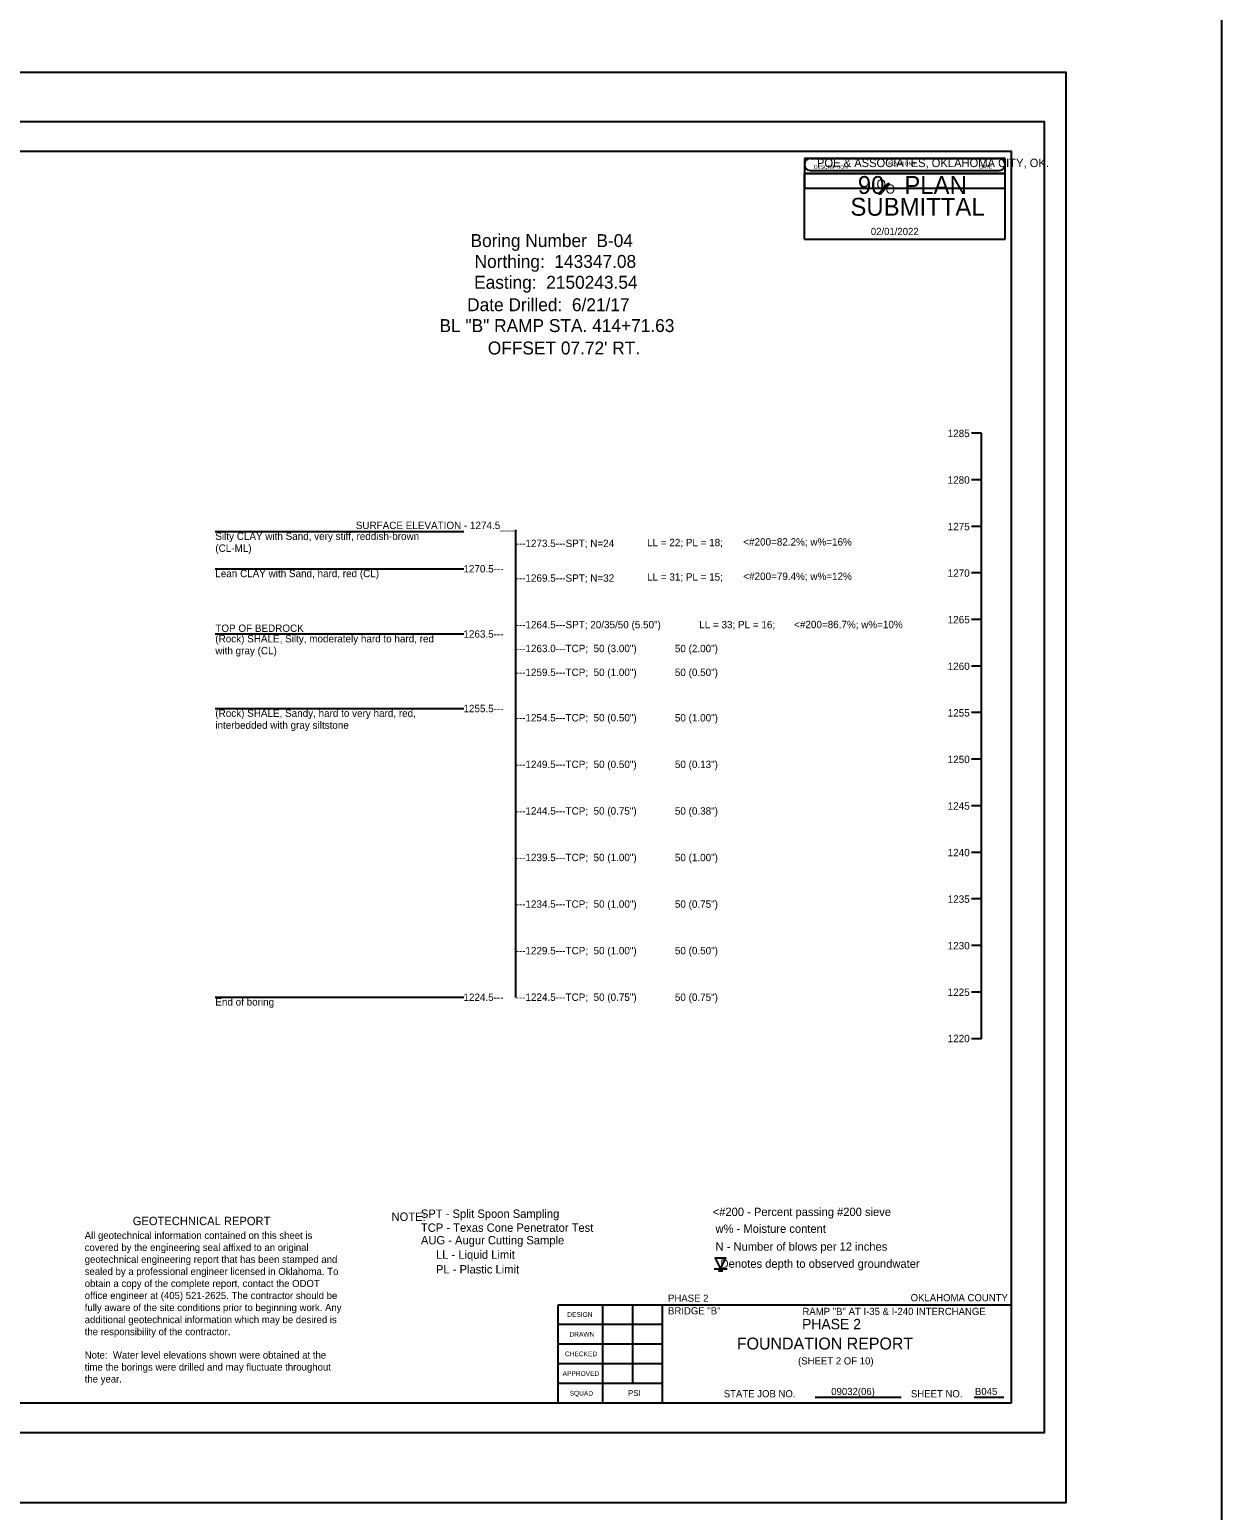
# Model space of a CAD drawing. Extents: x 2150162 to 2150245, y 143729 to 143865.
# Drawn here: x 2150183.41 to 2150203.4, y 143810.76 to 143835.6 of the extents above; entities that cross this region are included whole.
import ezdxf

# ---------------------------------------------------------------- set-up
doc = ezdxf.new("R2010")
doc.units = 0
for name, color, linetype in [('Default', 7, 'Continuous'), ('S', 7, 'Continuous'), ('SHT_Plot_Shape_Full', 7, 'Continuous'), ('SHT_Plot_Shape_Half', 7, 'Continuous'), ('SHT_Sheet_Border', 7, 'Continuous'), ('SHT_Stamp_90_Submit', 7, 'Continuous'), ('SHT_Stamp_Rev_Block', 7, 'Continuous'), ('SHT_Standard_Sheet_Lines', 7, 'Continuous'), ('SHT_Standard_Sheet_Txt', 7, 'Continuous'), ('T', 7, 'Continuous'), ('T-Title', 7, 'Continuous'), ('Text', 7, 'Continuous')]:
    doc.layers.add(name, color=color, linetype=linetype)

# ---------------------------------------------------------------- blocks, each defined once
blk = doc.blocks.new('DGRFC_WTLEV1')
at = {"layer": 'Default'}
for points in [[(-0.0127, 0), (0.0127, 0)], [(0, 0), (0.0106, 0.0212), (-0.0106, 0.0212), (0, 0)], [(-0.0042, -0.0042), (0.0042, -0.0042)]]:
    blk.add_lwpolyline(points, dxfattribs=at)

msp = doc.modelspace()

# ---------------------------------------------------------------- linework, layer by layer
at = {"layer": 'Default'}
msp.add_line((2150199.377, 143818.675), (2150199.377, 143828.832), dxfattribs=at)
for points in [[(2150199.377, 143828.832), (2150199.21, 143828.832)], [(2150199.377, 143828.05), (2150199.21, 143828.05)], [(2150199.377, 143827.269), (2150199.21, 143827.269)], [(2150186.527, 143827.183), (2150190.694, 143827.183)], [(2150191.561, 143827.209), (2150191.561, 143819.364)], [(2150186.527, 143826.558), (2150190.694, 143826.558)], [(2150199.377, 143826.488), (2150199.21, 143826.488)], [(2150199.377, 143825.707), (2150199.21, 143825.707)], [(2150186.527, 143825.464), (2150190.694, 143825.464)], [(2150199.377, 143824.925), (2150199.21, 143824.925)], [(2150186.527, 143824.214), (2150190.694, 143824.214)], [(2150199.377, 143824.144), (2150199.21, 143824.144)], [(2150199.377, 143823.363), (2150199.21, 143823.363)], [(2150199.377, 143822.582), (2150199.21, 143822.582)], [(2150199.377, 143821.8), (2150199.21, 143821.8)], [(2150199.377, 143821.019), (2150199.21, 143821.019)], [(2150199.377, 143820.238), (2150199.21, 143820.238)], [(2150186.527, 143819.37), (2150190.694, 143819.37)], [(2150199.377, 143819.457), (2150199.21, 143819.457)], [(2150199.377, 143818.675), (2150199.21, 143818.675)]]:
    msp.add_lwpolyline(points, dxfattribs=at)
at = {"layer": 'S'}
msp.add_lwpolyline([(2150203.404, 143784.341), (2150161.568, 143784.341), (2150161.568, 143865.061), (2150203.404, 143865.061)], close=True, dxfattribs=at)
at = {"layer": 'SHT_Plot_Shape_Full'}
msp.add_lwpolyline([(2150164.792, 143834.888), (2150200.792, 143834.888), (2150200.792, 143810.888), (2150164.792, 143810.888)], close=True, dxfattribs=at)
at = {"layer": 'SHT_Plot_Shape_Half'}
msp.add_lwpolyline([(2150166.429, 143834.063), (2150200.429, 143834.063), (2150200.429, 143812.063), (2150166.429, 143812.063)], close=True, dxfattribs=at)
at = {"layer": 'SHT_Sheet_Border'}
for p, q in [((2150192.279, 143812.563), (2150192.279, 143814.213)), ((2150192.279, 143814.213), (2150199.879, 143814.213)), ((2150194.029, 143812.563), (2150194.029, 143814.213))]:
    msp.add_line(p, q, dxfattribs=at)
msp.add_lwpolyline([(2150199.879, 143812.563), (2150168.379, 143812.563), (2150168.379, 143833.563), (2150199.879, 143833.563)], close=True, dxfattribs=at)
at = {"layer": 'SHT_Stamp_90_Submit'}
for p, q in [((2150196.51, 143833.438), (2150199.676, 143833.438)), ((2150196.41, 143833.188), (2150199.776, 143833.188)), ((2150196.41, 143832.089), (2150196.41, 143833.188)), ((2150196.51, 143833.238), (2150199.676, 143833.238)), ((2150199.776, 143832.089), (2150199.776, 143833.188)), ((2150197.653, 143832.85), (2150197.809, 143833.023)), ((2150197.671, 143832.85), (2150197.827, 143833.023)), ((2150197.676, 143832.85), (2150197.832, 143833.023)), ((2150197.684, 143832.85), (2150197.839, 143833.023)), ((2150197.809, 143833.023), (2150197.839, 143833.023)), ((2150197.653, 143832.85), (2150197.684, 143832.85)), ((2150196.41, 143832.089), (2150199.776, 143832.089))]:
    msp.add_line(p, q, dxfattribs=at)
for centre, start, end in [((2150196.51, 143833.339), 89.9952, 270), ((2150199.676, 143833.339), 270, 90.0048)]:
    msp.add_arc(centre, 0.1, start, end, dxfattribs=at)
at = {"layer": 'SHT_Stamp_Rev_Block'}
for p, q in [((2150196.41, 143833.438), (2150196.41, 143832.938)), ((2150199.776, 143833.438), (2150196.41, 143833.438)), ((2150199.776, 143832.938), (2150199.776, 143833.438)), ((2150199.776, 143833.188), (2150196.41, 143833.188)), ((2150199.776, 143832.938), (2150196.41, 143832.938))]:
    msp.add_line(p, q, dxfattribs=at)
at = {"layer": 'SHT_Standard_Sheet_Lines'}
for p, q in [((2150193.029, 143812.563), (2150193.029, 143814.213)), ((2150193.529, 143812.893), (2150193.529, 143814.213)), ((2150196.59, 143812.659), (2150198.03, 143812.659)), ((2150199.255, 143812.659), (2150199.757, 143812.659))]:
    msp.add_line(p, q, dxfattribs=at)
for points in [[(2150194.029, 143813.883), (2150192.279, 143813.883)], [(2150194.029, 143813.553), (2150192.279, 143813.553)], [(2150194.029, 143813.223), (2150192.279, 143813.223)], [(2150194.029, 143812.893), (2150192.279, 143812.893)]]:
    msp.add_lwpolyline(points, dxfattribs=at)

# ---------------------------------------------------------------- block references
at = {"layer": 'Default', "xscale": 8.503919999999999, "yscale": 8.503919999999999}
msp.add_blockref('DGRFC_WTLEV1', (2150195.003, 143814.814), dxfattribs=at)

# ---------------------------------------------------------------- texts
at = {"layer": 'Default'}
for s, height, p in [('Boring Number  B-04', 0.217, (2150190.808, 143831.955)), ('Northing:  143347.08', 0.217, (2150190.876, 143831.605)), ('Easting:  2150243.54', 0.217, (2150190.868, 143831.255)), ('Date Drilled:  6/21/17', 0.217, (2150190.751, 143830.879)), ('BL "B" RAMP STA. 414+71.63', 0.217, (2150190.288, 143830.529)), ("OFFSET 07.72' RT.", 0.217, (2150191.098, 143830.153)), ('1285', 0.124, (2150198.813, 143828.767)), ('1280', 0.124, (2150198.813, 143827.985)), ('SURFACE ELEVATION - 1274.5___', 0.124, (2150188.883, 143827.224)), ('1275', 0.124, (2150198.813, 143827.204)), ('Silty CLAY with Sand, very stiff, reddish-brown', 0.124, (2150186.527, 143827.042)), ('(CL-ML)', 0.124, (2150186.527, 143826.842)), ('---1273.5---SPT; N=24', 0.124, (2150191.564, 143826.922)), ('LL = 22; PL = 18;', 0.124, (2150193.77, 143826.936)), ('<#200=82.2%; w%=16%', 0.124, (2150195.384, 143826.947)), ('Lean CLAY with Sand, hard, red (CL)', 0.124, (2150186.527, 143826.417)), ('1270.5---', 0.124, (2150190.689, 143826.496)), ('LL = 31; PL = 15;', 0.124, (2150193.77, 143826.359)), ('<#200=79.4%; w%=12%', 0.124, (2150195.384, 143826.37)), ('1270', 0.124, (2150198.813, 143826.423)), ('---1269.5---SPT; N=32', 0.124, (2150191.564, 143826.34)), ('1265', 0.124, (2150198.813, 143825.642)), ('TOP OF BEDROCK', 0.124, (2150186.527, 143825.498)), ('1263.5---', 0.124, (2150190.689, 143825.402)), ('---1264.5---SPT; 20/35/50 (5.50")', 0.124, (2150191.564, 143825.559)), ('LL = 33; PL = 16;', 0.124, (2150194.645, 143825.559)), ('<#200=86.7%; w%=10%', 0.124, (2150196.237, 143825.561)), ('with gray (CL)', 0.124, (2150186.527, 143825.123)), ('(Rock) SHALE, Silty, moderately hard to hard, red', 0.124, (2150186.527, 143825.323)), ('---1263.0---TCP;  50 (3.00")', 0.124, (2150191.564, 143825.159)), ('50 (2.00")', 0.124, (2150194.236, 143825.158)), ('1260', 0.124, (2150198.813, 143824.86)), ('---1259.5---TCP;  50 (1.00")', 0.124, (2150191.564, 143824.759)), ('50 (0.50")', 0.124, (2150194.236, 143824.758)), ('1255.5---', 0.124, (2150190.689, 143824.152)), ('(Rock) SHALE, Sandy, hard to very hard, red,', 0.124, (2150186.527, 143824.073)), ('interbedded with gray siltstone', 0.124, (2150186.527, 143823.873)), ('---1254.5---TCP;  50 (0.50")', 0.124, (2150191.564, 143823.997)), ('50 (1.00")', 0.124, (2150194.236, 143823.996)), ('1255', 0.124, (2150198.813, 143824.079)), ('---1249.5---TCP;  50 (0.50")', 0.124, (2150191.564, 143823.215)), ('50 (0.13")', 0.124, (2150194.236, 143823.215)), ('1250', 0.124, (2150198.813, 143823.298)), ('---1244.5---TCP;  50 (0.75")', 0.124, (2150191.564, 143822.434)), ('50 (0.38")', 0.124, (2150194.236, 143822.433)), ('1245', 0.124, (2150198.813, 143822.517)), ('---1239.5---TCP;  50 (1.00")', 0.124, (2150191.564, 143821.653)), ('50 (1.00")', 0.124, (2150194.236, 143821.652)), ('1240', 0.124, (2150198.813, 143821.735)), ('1235', 0.124, (2150198.813, 143820.954)), ('---1234.5---TCP;  50 (1.00")', 0.124, (2150191.564, 143820.872)), ('50 (0.75")', 0.124, (2150194.236, 143820.871)), ('1230', 0.124, (2150198.813, 143820.173)), ('---1229.5---TCP;  50 (1.00")', 0.124, (2150191.564, 143820.09)), ('50 (0.50")', 0.124, (2150194.236, 143820.09)), ('1225', 0.124, (2150198.813, 143819.392)), ('End of boring', 0.124, (2150186.527, 143819.23)), ('1224.5---', 0.124, (2150190.689, 143819.308)), ('---1224.5---TCP;  50 (0.75")', 0.124, (2150191.564, 143819.309)), ('50 (0.75")', 0.124, (2150194.236, 143819.308)), ('1220', 0.124, (2150198.813, 143818.616))]:
    msp.add_text(s, height=height, dxfattribs=at).set_placement(p)
at = {"layer": 'Defpoints'}
msp.add_text('PHASE 2', height=0.175, dxfattribs=at).set_placement((2150196.369, 143813.8))
at = {"layer": 'SHT_Stamp_90_Submit'}
for s, height, p in [('POE & ASSOCIATES, OKLAHOMA CITY, OK.', 0.14, (2150196.62, 143833.296)), ('90   PLAN', 0.3, (2150197.305, 143832.846)), ('O', 0.153, (2150197.619, 143832.935)), ('O', 0.153, (2150197.771, 143832.851)), ('SUBMITTAL', 0.3, (2150197.181, 143832.48)), ('02/01/2022', 0.12, (2150197.523, 143832.157))]:
    msp.add_text(s, height=height, dxfattribs=at).set_placement(p)
at = {"layer": 'SHT_Stamp_Rev_Block'}
for s, height, p in [('DESCRIPTION', 0.05999, (2150196.57, 143833.267)), ('REVISIONS', 0.06, (2150197.818, 143833.326)), ('DATE', 0.06, (2150199.34, 143833.271))]:
    msp.add_text(s, height=height, dxfattribs=at).set_placement(p)
at = {"layer": 'SHT_Standard_Sheet_Txt'}
for s, height, p in [('DESIGN', 0.08, (2150192.431, 143814.008)), ('DRAWN', 0.08, (2150192.467, 143813.677)), ('CHECKED', 0.08, (2150192.392, 143813.347)), ('APPROVED', 0.08, (2150192.353, 143813.017)), ('SQUAD', 0.08, (2150192.471, 143812.687)), ('STATE JOB NO.', 0.12, (2150195.056, 143812.659)), ('SHEET NO. ', 0.12, (2150198.196, 143812.659))]:
    msp.add_text(s, height=height, dxfattribs=at).set_placement(p)
at = {"layer": 'T'}
for s, height, p in [('PHASE 2', 0.12, (2150194.121, 143814.262)), ('OKLAHOMA COUNTY', 0.12, (2150198.191, 143814.27)), ('BRIDGE "B"', 0.12, (2150194.121, 143814.05)), ('RAMP "B" AT I-35 & I-240 INTERCHANGE', 0.12, (2150196.376, 143814.04)), ('(SHEET 2 OF 10)', 0.12, (2150196.303, 143813.21)), ('09032(06)', 0.12, (2150196.859, 143812.697)), ('B045', 0.12, (2150199.27, 143812.697)), ('PSI', 0.1, (2150193.449, 143812.681))]:
    msp.add_text(s, height=height, dxfattribs=at).set_placement(p)
at = {"layer": 'T-Title'}
msp.add_text('FOUNDATION REPORT', height=0.2, dxfattribs=at).set_placement((2150195.276, 143813.461))
at = {"layer": 'Text'}
for s, height, p in [('    SPT - Split Spoon Sampling', 0.14, (2150189.768, 143815.669)), (' <#200 - Percent passing #200 sieve', 0.14, (2150194.818, 143815.7)), ('GEOTECHNICAL REPORT', 0.14, (2150185.142, 143815.547)), ('NOTE:', 0.14, (2150189.483, 143815.619)), ('    TCP - Texas Cone Penetrator Test', 0.14, (2150189.768, 143815.435)), ('w% - Moisture content', 0.14, (2150194.918, 143815.418)), ('All geotechnical information contained on this sheet is ', 0.12, (2150184.336, 143815.315)), ('    AUG - Augur Cutting Sample', 0.14, (2150189.768, 143815.225)), ('covered by the engineering seal affixed to an original ', 0.12, (2150184.336, 143815.113)), (' LL - Liquid Limit', 0.14, (2150190.177, 143814.982)), ('N - Number of blows per 12 inches', 0.14, (2150194.918, 143815.118)), ('sealed by a professional engineer licensed in Oklahoma. To ', 0.12, (2150184.336, 143814.711)), ('geotechnical engineering report that has been stamped and ', 0.12, (2150184.336, 143814.913)), (' PL - Plastic Limit', 0.14, (2150190.177, 143814.736)), ('    Denotes depth to observed groundwater', 0.14, (2150194.794, 143814.831)), ('obtain a copy of the complete report, contact the ODOT ', 0.12, (2150184.336, 143814.509)), ('office engineer at (405) 521-2625. The contractor should be ', 0.12, (2150184.336, 143814.307)), ('fully aware of the site conditions prior to beginning work. Any ', 0.12, (2150184.336, 143814.105)), ('the responsibility of the contractor.', 0.12, (2150184.336, 143813.701)), ('additional geotechnical information which may be desired is ', 0.12, (2150184.336, 143813.903)), ('Note:  Water level elevations shown were obtained at the ', 0.12, (2150184.336, 143813.309)), ('time the borings were drilled and may fluctuate throughout ', 0.12, (2150184.336, 143813.107)), ('the year.', 0.12, (2150184.336, 143812.907))]:
    msp.add_text(s, height=height, dxfattribs=at).set_placement(p)

doc.saveas('drawing.dxf')
